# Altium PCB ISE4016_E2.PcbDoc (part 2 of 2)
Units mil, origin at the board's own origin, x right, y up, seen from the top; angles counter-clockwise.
Board outline 5600 x 2000 mil, 4 copper layers (Top Layer, InternalPlane1, MidLayer2, Bottom Layer), stack 59 mil thick; 110 components, 63 nets, 365 pads, 250 vias.
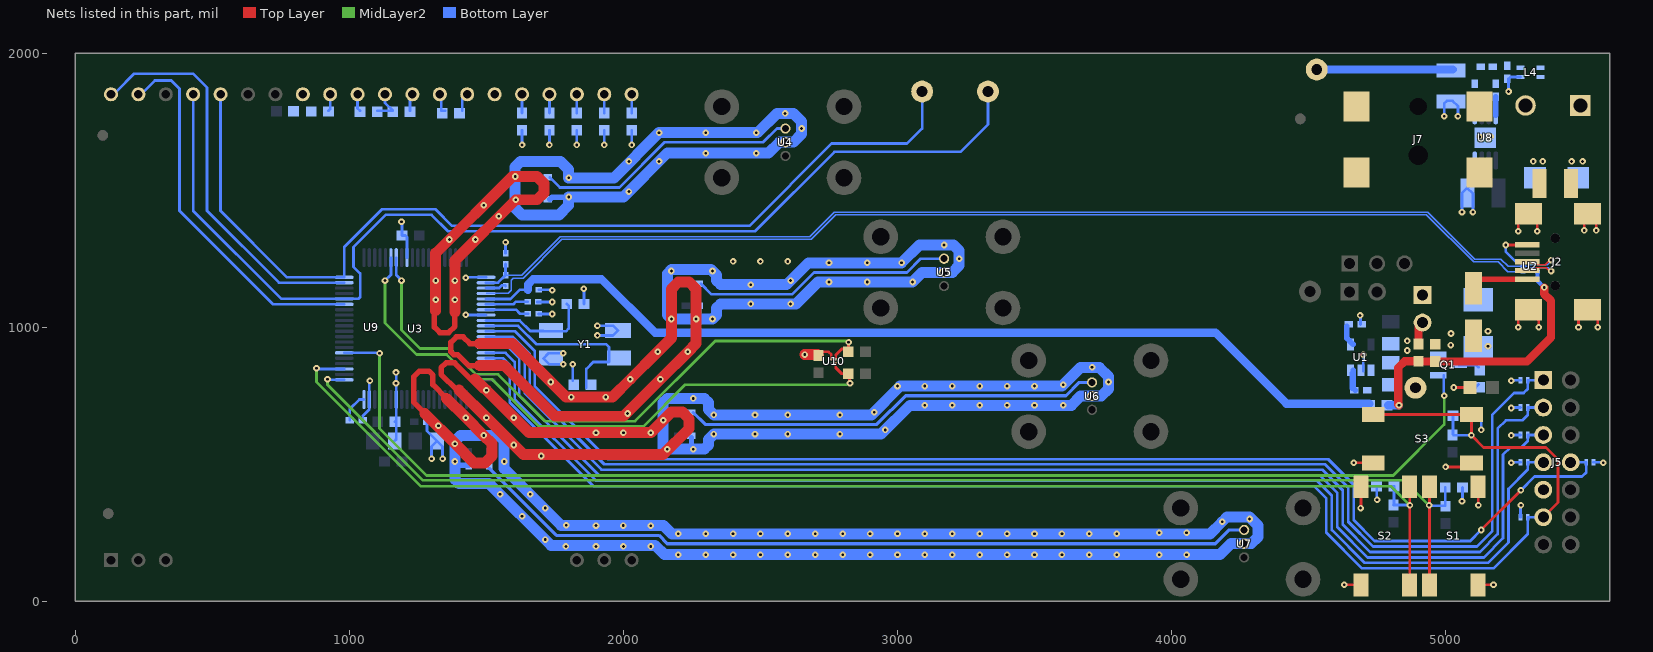
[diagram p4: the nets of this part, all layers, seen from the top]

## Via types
v1: diameter 24, hole 10, Top Layer to Bottom Layer, tented both sides, 246 vias
v2: diameter 22, hole 10, Top Layer to Bottom Layer, tented both sides, 4 vias

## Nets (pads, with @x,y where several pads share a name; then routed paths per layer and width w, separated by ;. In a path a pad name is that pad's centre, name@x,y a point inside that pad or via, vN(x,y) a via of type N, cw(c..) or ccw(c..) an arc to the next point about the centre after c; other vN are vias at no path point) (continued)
GND: C1.2 C2.2 C3.2 C4.2 C5.2 C6.2 C7.2 C8.2 C9.2 C10.2 C11.2 C12.2 C13.2 C14.2 C15.2 C16.2 C17.2 C18.2 C19.2 C21.2 C22.2 C23.2 C24.2 C28.2 C29.2 C30.2 C31.2 C32.2 C33.2 C34.2 C35.2 C36.2 C37.2 C38.2 D1.2 D2.2 D3.2 D4.2 D5.2 D7.2 D8.2 J2.5 J2.6 J2.7 J2.8 J2.9 J5.9 L4.3 Q1.2 R5.2 S1.3 S1.4 S2.3 S2.4 S3.3 S3.4 U1.2 U2.3 U3.14 U3.19 U3.49 U3.61 U3.68 U4.2 U5.2 U6.2 U7.2 U8.4 U8.9 U9.26 U9.33 U10.A2 Y1.2 Y1.4 | length 27028.8
  Top Layer w10: C38.2@2711.65,896.5 2725.16,910 2748.65,910 2758.65,900 U10.A2@2758.65,882.87 ; v1(4630,60) 4690.79,60 S2.4@4691.73,59.06 ; v1(4665,505) 4735.79,505 S3.3@4736.18,504.61 ; v1(4690,340) 4691.73,341.73 S2.3@4691.73,417.32 ; v1(5000,490) 5079.84,490 S3.4@5094.45,504.61 ; S1.3@5118.9,59.06 5119.84,60 v1(5175,60) ; S1.4@5118.9,417.32 5118.9,351.1 v1(5120,350) ; v1(5220,1300) J2.5@5291.77,1300 ; v1(5265,1000) 5265,1026.1 J2.9@5301.89,1062.99 5340,1024.88 v1(5340,1000) ; v1(5265,1350) J2.6@5265,1376.5 ; J2.6@5300,1386.5 J2.6@5336.89,1423.39 ; v1(5335,1350) J2.6@5335,1380.28 ; v1(5485,1000) 5485,1029.57 J2.8@5518.43,1062.99 5555,1026.42 v1(5555,1000) ; v1(5506,1353) J2.7@5506,1377.96 ; J2.7@5515,1384.96 J2.7@5553.43,1423.39 ; v1@5550,1350 J2.7@5550,1381.81
  Top Layer w20: 1285,675.5 1235,725.5 1235,820 1255,840 1290,840 1305,825 1305,790 1355,740 ; 1315,1055 1310,1050 1310,1000 1330,980 1362.43,980 1385,1002.57 1385,1050 ; 1400,770 1392.57,770 1335,827.57 1335,852.43 1352.57,870 1384,870 1486.5,767.5 ; 1475,860 1435,860 1395,900 1380,900 1370,910 1370,945 1390,965 1415,965 1440,940 1475,940
  Top Layer w40: 1275,685 v1(1385,575) 1455,505 1495,505 1520,530 1520,575 v1(1490,605) v1(1425,670) 1355,740 ; 1315,1060 1315,1270 1595,1550 1685,1550 1710,1525 1710,1490 1685,1465 v1(1607,1465) 1385,1243 1385,1056 ; 1400,770 v1(1500,670) v1(1600,570) 1635,535 2145,535 2240,630 2240,665 2215,690 2175,690 v1(2145,660) v1(2100,615) v1(2000,615) v1(1900,615) 1655,615 v1(1600,670) v1(1500,770) 1458.5,811.5 ; 1475,860 1565,860 1750,675 2000,675 v1(2135,810) v1(2235,910) 2265,940 v1(2265,1030) 2265,1140 2240,1165 2200,1165 2175,1140 2175,960 v1(2125,910) v1(2025,810) 1960,745 1790,745 1595,940 1475,940 ; v1(2661.65,900) 2708.15,900 C38.2@2711.65,896.5
  Bottom Layer w10: C11.2@1048.62,660 1048.62,676.49 1072.68,700.55 U3.19@1072.68,736.14 1072.68,802.68 v1(1075,805) ; C14.2@1165,585 1171.1,591.1 C16.2@1171.1,659.61 ; C16.2@1166.5,655 C16.2@1171.1,659.61 ; v1(1170,835) 1171.1,833.9 U3.14@1171.1,736.14 C16.2@1171.1,659.61 ; v1(1190,1385) 1191.53,1383.47 C15.2@1191.53,1334.4 1204.6,1334.4 1210.47,1328.53 U3.49@1210.47,1253.86 ; C17.2@1283.62,655 1283.62,621.38 C18.2@1320,585 ; v1(1300,520) 1300,565 C18.2@1320,585 ; v1(1340,520) 1340,565 C18.2@1320,585 ; v1(1425,1045) 1425.79,1044.21 U3.68@1498.86,1044.21 ; v1(1425,1180) 1427.01,1182.01 U3.61@1498.86,1182.01 ; R5.2@1570,1269.69 v1(1570,1310) ; v1(1630,1665) C29.2@1630,1718.5 ; C13.2@1685.69,1092 v1@1735,1092 ; C10.2@1690,1048 v1@1738.31,1048 ; C12.2@1690.69,1137 1738,1137 v1(1740,1135) ; v1(1730,1665) C30.2@1730,1718.5 ; v1(1780,865) 1728.98,865 1707.98,886 1726.98,905 v1(1780,905) ; C9.2@1815,805 v1(1815,865) ; v1(1830,1665) C31.2@1830,1718.5 ; v1(1855,1140) 1856.5,1138.5 C7.2@1856.5,1085 ; v1(1905,970) 1962.08,970 Y1.4@1980.08,988 1963.08,1005 v1(1905,1005) ; v1(1930,1665) C32.2@1930,1718.5 ; v1(2030,1665) C33.2@2030,1718.5 ; v1@4686.62,1041.62 v1(4688,1043) ; C4.2@4690,1010 v1@4690,1040 ; U1.2@4700,840 v1@4700,897.24 ; C8.2@4748.5,420 4748.5,371.5 v1(4750,370) ; v1(4995,1770) 4995,1816.26 5004.84,1826.1 5026.02,1826.1 5045,1807.13 v1(5045,1770) ; v1(5060,365) 5061.5,366.5 C6.2@5061.5,415 ; v1(5060,1420) 5060,1489.25 C23.2@5078.94,1508.19 ; C19.2@5089.82,677.27 5122.73,677.27 5130,670 v1(5130,625) ; v1(5100,1420) 5100,1487.13 C23.2@5078.94,1508.19 ; U8.4@5107.64,1610.51 5107.64,1536.89 C23.2@5078.94,1508.19 ; v1(5220,1300) 5220,1275 5253.31,1241.68 U2.3@5282.43,1241.68 ; v1(5230,1860) 5230,1906.38 5236.89,1913.27 L4.3@5273.58,1913.27 ; v1@5235,605 5236.81,606.81 D3.2@5273.3,606.81 ; v1(5240,505) 5241.81,506.81 D4.2@5273.3,506.81 ; v1(5240,705) 5241.81,706.81 D2.2@5273.3,706.81 ; v1(5240,805) 5241.81,806.81 D1.2@5273.3,806.81 ; D8.2@5273.3,306.81 5273.3,348.3 v1(5275,350) ; D5.2@5540.07,506.81 5573.19,506.81 v1(5575,505)
  Bottom Layer w20: v1(1385,510) 1398.62,496.38 C37.2@1436,496.38 ; C34.2@1731.5,1466.3 1740.2,1475 v1(1800,1475) ; C36.2@2248.35,597.2 2248.35,561.65 v1(2255,555) ; v1@2275.55,1030 C35.2@2275.55,1072.2
  Bottom Layer w40: v1(1791,277) 1773,277 1565,485 1565,585 1545,605 v1(1490,605) 1405,605 1385,585 v1(1385,575) v1(1385,510) 1385,445 1400,430 1510,430 1736.41,203.59 2115.94,203.59 2149.53,170 4177,170 4217,210 U7.2@4265,210 4291,210 4315,234 4315,276.04 4284.34,306.7 4201.7,306.7 v1(4185,290) 4141,246 2177,246 2146,277 v1@1793,277 ; v1(2265,1030) v1(2175,1030) 2160,1045 2160,1195 2175,1210 2320,1210 2340,1190 2340,1170 2355,1155 2595,1155 2675,1235 v1(3015,1235) 3080,1300 3205,1300 3225,1280 3225,1225 3200,1200 U5.2@3170.2,1200 ; v1@2275.55,1030 v1(2325,1030) 2340,1045 2340,1070 2355,1085 2630,1085 2710,1165 v1(3055,1165) 3090,1200 U5.2@3170,1200 ; U4.2@2591,1675 2620,1675 2650,1705 2650,1750 2620,1780 2560,1780 2490,1710 v1(2130,1710) 1965,1545 v1(1800,1545) 1800,1575 1770,1605 1625,1605 1605,1585 1605,1435 1630,1410 1765,1410 1800,1445 v1(1800,1475) 2000,1475 2160,1635 2529,1635 2569,1675 U4.2@2598.38,1675 ; 2145,560 2150,555 v1(2160,555) v1(2255,555) 2295,555 2310,570 2310,590 v1(2330,610) v1(2600,610) 2940,610 3045,715 3635,715 3668.54,748.54 U6.2@3710,748.54 3743.55,748.55 3770,775 3770,820 3736.46,853.54 v1(3710,853.54) 3668.54,853.54 3600,785 v1(3500,785) v1(3400,785) v1(3300,785) v1(3200,785) v1(3100,785) 3010,785 2905,680 v1(2330,680) 2310,700 2310,725 2295,740 2160,740 2145,725 v1(2145,660) 2145,560
  other v1: 2200,170 2300,170 2400,170 2500,170 2600,170 2700,170 2800,170 2900,170 3000,170 3100,170 3200,170 3300,170 3400,170 3500,170 3600,170 3700,170 3800,170 3955,170 4055,170 1790,200 1900,200 2000,200 2100,200 1715,225 2200,246 2300,246 2400,246 2500,246 2600,246 2700,246 2800,246 2900,246 3000,246 3100,246 3200,246 3300,246 3400,246 3500,246 3600,246 3700,246 3800,246 3955,250 4055,250 2100,275 1900,276 1999,276 4285,300 1630,310 1715,340 1550,390 1660,390 1565,510 1700,530 5240,605 2480,610 2790,610 2955,625 1325,640 2480,680 2600,680 2790,680 2015,685 2915,690 3100,715 3200,715 3300,715 3400,715 3500,715 3605,715 2255,740 1810,745 1935,745 3000,785 3605,790 1170,795 1735,800 3770,800 4700,900 4860,915 5155,930 5019,934.73 4860,950 5020,977 5155,985 1740,1048 2465,1085 2610,1085 1740,1092 1315,1100 1385,1100 2465,1155 2750,1165 2890,1165 1315,1170 1385,1170 2610,1170 2175,1205 2325,1205 2750,1235 2890,1235 2400,1240 2500,1240 2600,1240 3225,1250 3170,1300 1365,1320 1460,1320 5550,1353 1545,1405 1490,1445 2020,1495 1605,1550 2020,1605 2130,1605 2300,1635 2485,1635 5125,1695 5165,1695 2300,1710 2485,1710 2650,1725 2590,1780
NCS_DISP: U3.39 U9.40 | length 1457.6
  Bottom Layer w10: U9.40@130,1860 150,1860 215,1925 430,1925 480,1875 480,1425 742.68,1162.32 U3.39@981.14,1162.32
NetC4_1: C4.1 U1.4 | length 75.7
  Bottom Layer w20: C4.1@4640,1003.62 4640,959.84 4650,949.84 U1.4@4662.6,937.24
NetC5_1: C5.1 D7.1 J1.1 J2.1 | length 119
  Top Layer w20: 5134,1175 J2.1@5252.95,1175
NetC13_1: C13.1 U3.66 | length 155.4
  Bottom Layer w10: U3.66@1498.86,1083.58 1598.58,1083.58 1608,1093 C13.1@1650.32,1093
NetC20_1: C20.1 D10.2 J6.1 J7.1 J7.1A L4.1
  other v1: 5460,1605 5500,1605
NetC20_2: C20.2 D10.1 J6.2 J7.2 J7.3 L4.4
  other v1: 5320,1605 5355,1605
NetC21_1: C21.1 D9.2 L4.2
NetC25_1: C25.1 U9.31 | length 73.5
  Bottom Layer w10: U9.31@1030,1860 1030,1798.5 C25.1@1038.5,1790
NetC25_2: C25.2 C26.1 U9.30 | length 138.8
  Bottom Layer w10: C25.2@1101.5,1790 1158.5,1790 1130,1818.5 U9.30@1130,1860
NetC26_2: C26.2 U9.29 | length 73.5
  Bottom Layer w10: C26.2@1221.5,1790 1221.5,1851.5 U9.29@1230,1860
NetC27_1: C27.1 U9.28 | length 85.6
  Bottom Layer w10: U9.28@1330,1860 1335,1855 1335,1790 C27.1@1348.5,1790
NetC27_2: C27.2 U9.27 | length 77.7
  Bottom Layer w10: C27.2@1411.5,1790 1411.5,1841.5 U9.27@1430,1860
NetC28_1: C28.1 U9.32 | length 72.7
  Bottom Layer w10: C28.1@923.45,1790 930,1796.56 U9.32@930,1860
NetC29_1: C29.1 U9.25 | length 78.5
  Bottom Layer w10: C29.1@1630,1781.5 U9.25@1630,1860
NetC30_1: C30.1 U9.24 | length 78.5
  Bottom Layer w10: C30.1@1730,1781.5 U9.24@1730,1860
NetC31_1: C31.1 U9.23 | length 78.5
  Bottom Layer w10: C31.1@1830,1781.5 U9.23@1830,1860
NetC32_1: C32.1 U9.22 | length 78.5
  Bottom Layer w10: C32.1@1930,1781.5 U9.22@1930,1860
NetC33_1: C33.1 U9.21 | length 78.5
  Bottom Layer w10: C33.1@2030,1781.5 U9.21@2030,1860
NetD6_2: D6.2 R3.2 | length 163.7
  Top Layer w10: v1(5030,780) D6.2@5098.66,780
  Bottom Layer w10: v1(5030,780) 5109.76,780 R3.2@5120.53,790.77
NetJ1_2: J1.2 L1.1 | length 84.7
  Top Layer w30: L1.1@4901,938.5 4901,1002 J1.2@4916,1017
NetQ1_1: Q1.1 U3.26 | length 4606.8
  MidLayer2 w10: v1(1110,905) 1110,630 1281,459 4809,459 4995,645 v1@4995,747
  Bottom Layer w10: U3.26@981.14,906.42 1099.58,906.42 v1@1100,906 ; v1@4993.13,747 Q1.1@4993.13,824.87
  other v1: 4995,750
NetQ1_3: Q1.3 R3.1 | length 76.1
  Bottom Layer w10: Q1.3@5047.93,862.27 5112.03,862.27 R3.1@5120.53,853.77
NetR1_1: R1.1 U1.3 | length 129.8
  Bottom Layer w20: R1.1@4659.38,778 4660,778 U1.3@4660,831.35 ; U1.3@4662.6,842.76 4662.6,777.4 R1.1@4670,770
NetR8_2: R8.2 U8.8 | length 67.7
  Bottom Layer w20: U8.8@5183.39,1773.68 R8.2@5183.39,1841.38
NetR9_2: R9.2 U8.5 | length 68.3
  Bottom Layer w20: U8.5@5106.61,1773.68 5107.2,1774.26 R9.2@5107.2,1841.78
NetR10_1: R10.1 U4.3 | length 963.6
  Bottom Layer w10: R10.1@1731.5,1546.3 1767.8,1510 1985,1510 2150,1675 2510,1675 2560,1725 U4.3@2591,1725
NetR11_1: R11.1 U5.3 | length 957.8
  Bottom Layer w10: R11.1@2282.05,1158.7 2320.75,1120 2615,1120 2695,1200 3035,1200 3085,1250 U5.3@3170,1250
NetR12_1: R12.1 U6.3 | length 1543.9
  Bottom Layer w12: R12.1@2254.84,688.7 2298.54,645 2925,645 3030,750 3615,750 3663.54,798.54 U6.3@3710,798.54 ; U6.3@3715,793.54 U6.3@3720,798.54
NetR13_1: R13.1 U7.3 | length 2889.9
  Bottom Layer w12: R13.1@1510,485.57 1755.57,240 2130,240 2160,210 4160,210 4210,260 U7.3@4265,260
NRST_DISP: U3.35 U9.39 | length 1366.6
  Bottom Layer w10: U9.39@230,1860 250,1860 290,1900 350,1900 380,1870 380,1425 721.42,1083.58 U3.35@981.14,1083.58
NRST_MSP: C19.1 D8.1 J5.11 R7.1 S3.1 S3.2 U3.76 | length 5599.6
  Top Layer w10: S3.1@4736.18,681.77 S3.2@5094.45,681.77 v1(5094.45,605.55) 5138.67,561.33 5366.48,561.33 5410,517.81 5410,360.13 J5.11@5356.69,306.81
  Bottom Layer w10: U3.76@1498.86,886.73 1560.27,886.73 1585,862 1585,725 1890,420 4520,420 4565,375 4565,250 4695,120 5175,120 5300.07,245.07 D8.1@5300.07,306.81 J5.11@5356.69,306.81 ; C19.1@5026.83,677.27 5026.83,608.33 5029.61,605.55 v1(5094.45,605.55)
PUR_1: R6.1 U3.63 | length 76.5
  Bottom Layer w10: U3.63@1498.86,1142.64 1546.54,1142.64 1556.8,1152.9 1567.41,1152.9 R6.1@1570,1150.32
SCL_DISP: TP5.1 U3.36 U9.37 | length 4031.8
  Bottom Layer w10: U9.37@430,1860 430,1425 750.95,1104.05 1034.05,1104.05 1039.2,1109.2 1039.2,1195.8 1015,1220 1015,1292.5 1132.5,1410 1300,1410 1360,1350 2480,1350 2770,1640 3230,1640 3330,1740 3330,1835 TP5.1@3320,1845
SCL_TEMP: R14.1 U3.47 U10.B2 | length 2265.9
  Top Layer w10: U10.B2@2774.65,882.87 2774.65,898 2796.65,920 R14.1@2815.16,920 ; v1(2821.65,945) 2821.65,913.5 R14.1@2825.16,910
  MidLayer2 w10: v1(1190,1170) 1190,990 1257.5,922.5 1367.5,922.5 1462,828 1542,828 1713,657 2042,657 2335,950 2816.65,950 v1(2821.65,945)
  Bottom Layer w10: U3.47@1171.1,1253.86 1171.1,1190 1190,1171.1 v1(1190,1170)
SDA_TEMP: R15.1 U3.46 U10.B1 | length 2265.9
  Top Layer w10: U10.B1@2774.65,867.13 2774.65,852 2796.65,830 R15.1@2815.16,830 ; R15.1@2825.16,830 2825.16,796.5 v1(2826.65,795)
  MidLayer2 w10: v1(1130,1170) 1130,1015 1245,900 1355,900 1445,810 1520,810 1692,638 2073,638 2225,790 2821.65,790 v1(2826.65,795)
  Bottom Layer w10: v1(1130,1170) 1151.42,1191.42 U3.46@1151.42,1253.86
SI_DISP: TP4.1 U3.40 U9.36 | length 3570.4
  Bottom Layer w10: U9.36@530,1860 530,1425 772.99,1182.01 U3.40@981.14,1182.01 981.14,1293.14 1118,1430 1315,1430 1375,1370 2460,1370 2760,1670 3035,1670 3090,1725 TP4.1@3090,1860
TCK: D4.1 J5.7 U3.75 | length 4610
  Bottom Layer w10: U3.75@1498.86,906.42 1569.58,906.42 1603,873 1603,737 1900,440 4530,440 4585,385 4585,260 4705,140 5155,140 5230,215 5230,410 5300.07,480.07 D4.1@5300.07,506.81 J5.7@5356.69,506.81
TDI: D2.1 J5.3 U3.73 | length 4786.5
  Bottom Layer w10: U3.73@1498.86,945.79 1586.21,945.79 1640,892 1640,760 1920,480 4550,480 4625,405 4625,280 4725,180 5125,180 5190,245 5190,630 5220,660 5280,660 5300.07,680.07 D2.1@5300.07,706.81 J5.3@5356.69,706.81 J5.3@5356.69,705.32
TDO: D1.1 J5.1 U3.72 | length 4843.2
  Bottom Layer w10: U3.72@1498.86,965.47 1594.53,965.47 1658,902 1658,772 1930,500 4560,500 4645,415 4645,290 4735,200 5115,200 5170,255 5170,680 5250,760 5285,760 5300.07,775.07 D1.1@5300.07,806.81 J5.1@5356.69,806.81
TEST_MSP: D5.1 J5.8 U3.71 | length 4679.4
  Top Layer w10: v1(5130,260) v1(5275,405)
  Bottom Layer w10: U3.71@1498.86,985.16 1604.84,985.16 1676,914 1676,785 1943,518 4572,518 4665,425 4665,296.21 4741.21,220 5090,220 v1(5130,260) ; v1(5275,405) 5325,455 5498.3,455 5513.3,470 D5.1@5513.3,506.81 J5.8@5456.69,506.81
TMS: D3.1 J5.5 U3.74 | length 4704.5
  Bottom Layer w10: U3.74@1498.86,926.1 1579.9,926.1 1620,886 1620,750 1910,460 4540,460 4605,395 4605,270 4715,160 5140,160 5210,230 5210,535 5236.33,561.33 5276.33,561.33 5300.07,585.07 D3.1@5300.07,606.81 J5.5@5356.69,606.81
USB_D_N: J2.2 U2.1 U3.64 | length 4194.1
  Top Layer w5.3: J2.2@5327,1206.69 5327,1212 5332.7,1217.7 5367.27,1217.7 5379.97,1205 v1(5385,1205)
  Bottom Layer w5.3: U3.64@1498.86,1122.95 1579.35,1122.95 1590.49,1134.09 1590.49,1171.79 1598.09,1179.39 1633.95,1179.39 1774.57,1320 2684.57,1320 2774.27,1409.7 4930.3,1409.7 5102,1238 5192,1238 5227.69,1202.31 U2.1@5282.43,1202.31 5283.11,1203 5297,1203 5310,1216 5374,1216 v1(5385,1205)
USB_D_P: J2.3 R5.1 R6.2 U2.2 U3.62 | length 4203.2
  Top Layer w5.3: J2.3@5325,1238.19 5325,1235 5332,1228 5363,1228 5380,1245 v1(5385,1245)
  Bottom Layer w5.3: R6.2@1570,1189.69 1629.69,1189.69 1770.3,1330.3 2680.3,1330.3 2770,1420 4934.57,1420 5106.27,1248.3 5201.7,1248.3 5228,1222 U2.2@5282.43,1222 5301.43,1222 5306.43,1227 5372,1227 5387.5,1242.5 v1(5385,1245)
  Bottom Layer w10: U3.62@1498.86,1162.32 1541.97,1162.32 1569.33,1189.69 R6.2@1570,1189.69 R5.1@1570,1230.32
USER_BUTTON1: C6.1 R2.1 S1.1 S1.2 U3.21 | length 4768.8
  Top Layer w10: S1.1@4941.73,59.06 S1.2@4941.73,417.32
  MidLayer2 w10: v1(920,810) 920,790 1269,441 4849,441 v1(4940,350)
  Bottom Layer w10: v1(920,810) 922.01,807.99 U3.21@981.14,807.99 ; v1(4940,350) 4942.01,347.99 4998.5,347.99 C6.1@4998.5,415
USER_BUTTON2: C8.1 R4.1 S2.1 S2.2 U3.23 | length 4816.6
  Top Layer w10: S2.2@4868.9,59.06 S2.1@4868.9,417.32
  MidLayer2 w10: v1(880,850) 880,800 1260,420 4800,420 v1(4870,350)
  Bottom Layer w10: v1(880,850) 882.64,847.36 U3.23@981.14,847.36 ; C8.1@4811.5,420 4811.5,352.99 R4.1@4810,351.5 4868.5,351.5 v1(4870,350)
V18_1: C10.1 U3.67 | length 158.6
  Bottom Layer w10: U3.67@1498.86,1063.9 1608.1,1063.9 1623,1049 C10.1@1651.32,1049
VBUS: C2.1 L1.2 L2.1 U2.5 | length 1039.6
  Top Layer w30: v1(4830,715) 4827,718 4827,852 4850.5,875.5 L1.2@4901,875.5 ; L1.2@4901,874.33 5297.11,874.33 5385,962.22 5385,1096.75 5360,1121.75 v1(5360,1145)
  Bottom Layer w15: U2.5@5335.57,1200 5335.57,1169.43 v1(5360,1145)
  Bottom Layer w30: L2.1@4791,715 v1(4830,715)
VBUS_FLT: C3.1 C12.1 L2.2 R1.2 TP1.1 U1.1 U3.65 | length 3452
  Bottom Layer w10: U3.65@1498.86,1103.27 1588.27,1103.27 1622,1137 C12.1@1651.32,1137
  Bottom Layer w30: C12.1@1651.32,1137 1651.32,1156.32 1670,1175 1920,1175 2115,980 4160,980 4419,721 L2.2@4721.82,721
VCORE1: C11.1 U3.20 | length 107.4
  Bottom Layer w10: C11.1@1001.38,660 1001.38,701.38 1036.14,736.14 U3.20@1052.99,736.14
VIN_24V: C22.1 D9.1 R8.1 R9.1 TP3.1 | length 496.1
  Bottom Layer w30: TP3.1@4529.88,1940.28 C22.1@5026.02,1940.28
XT2IN1: C7.1 U3.69 Y1.1 | length 455.3
  Bottom Layer w10: U3.69@1498.86,1024.53 1621.47,1024.53 1660,986 1707.98,986 Y1.1@1708.98,985 ; 1668,985 Y1.1@1708.98,985 ; C7.1@1793.5,1085 1800,1078.5 1800,995 1790,985 Y1.1@1708.98,985
XT2OUT1: C9.1 U3.70 Y1.3 | length 695
  Bottom Layer w10: U3.70@1498.86,1004.84 1615.16,1004.84 1682,938 1936,938 1947.02,926.98 1947.02,873 1890,873 1864.5,847.5 C9.1@1864.5,780
pads on no net: FID1.1 FID2.1 FID3.1 FID4.1 FID5.1 FID6.1 J2.4 J2.10 J2.11 J5.2 J5.6 J5.10 J5.12 J5.13 J5.14 J7.MH1 J7.MH2 SH-J1.0 SH-J2.0 U2.4 U3.1 U3.2 U3.3 U3.4 U3.5 U3.6 U3.7 U3.8 U3.9 U3.10 U3.12 U3.13 U3.15 U3.16 U3.17 U3.22 U3.24 U3.25 U3.27 U3.28 U3.29 U3.30 U3.31 U3.32 U3.33 U3.37 U3.38 U3.41 U3.42 U3.43 U3.44 U3.45 U3.48 U3.51 U3.52 U3.53 U3.54 U3.55 U3.56 U3.57 U3.58 U3.59 U3.60 U8.2 U8.3 U8.6 U8.7 U9.1 U9.2 U9.3 U9.18 U9.19 U9.20 Z1.1 Z1.2 Z1.3 Z1.4 Z2.1 Z2.2 Z2.3 Z2.4 Z3.1 Z3.2 Z3.3 Z3.4 Z4.1 Z4.2 Z4.3 Z4.4

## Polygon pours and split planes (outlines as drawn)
GND on MidLayer2 "GND" (solid, remove dead copper, pour order 3): 10,1990 10,10 5590,10 5590,1990
NetC20_1 on Top Layer "GND" (solid, remove dead copper, pour order 4): 5200,1530 5200,1890 5445,1890 5445,1485 5575,1485 5575,1970 5050,1970 5050,1530
GND on InternalPlane1 (split plane): 5579.9,20.1 20.1,20.1 20.1,1979.9 5579.9,1979.9

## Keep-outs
Keep-Out Layer:
  text ".Layer_Name" at 577,-858.49 h60

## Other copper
Top Layer:
  region net NetC5_1: 4875,1160 5030,1160 5030,1220 5175,1220 5175,1045 4960,1045 4960,1065 4875,1065
  region net GND: 4935,960 4935,905 5190,905 5190,1030 5000,1030 5000,960
  region net NetC20_2: 4615,1900 4615,1440 5230,1440 5230,1460 5235,1465 5390,1465 5395,1470 5395,1839 5217,1839 5217,1500 4750,1500 4750,1900
  text ".Layer_Name" at 577,-858.49 h60
MidLayer2:
  text ".Layer_Name" at 577,-858.49 h60
Bottom Layer:
  region net +3P3_USB: 4560,1305 4560,1210 4410,1210 4410,1065 4700,1065 4700,1305
  region net +3P3V: 1080,675 1125,675 1125,545 1155,545 1155,470 990,470 990,635 1080,635
  region net AVCC: 1205,680 1205,545 1165,545 1165,470 1270,470 1270,630 1255,630 1255,680
  region net GND: 780,1885 780,1755 885,1755 885,1885
  region net NetC25_2: 1080,1890 1080,1755 1185,1755 1185,1890
  region net GND: 5180,1025 5000,1025 5000,965 4760,965 4760,840 4835,840 4835,885 5180,885
  region net VIN_24V: 4950,1970 4950,1870 5190,1870 5190,1920 5144,1920 5144,1970
  region net NetC21_1: 5155,1935 5300,1935 5300,1980 5155,1980
  region net VBUS_FLT: 4720,870 4720,810 4690,810 4690,690 4745,690 4745,760 4850,760 4850,735 4935,735 4935,820 4750,820 4750,870
  region net NetC5_1: 4880,1145 4880,1075 5045,1075 5045,1045 5175,1045 5175,1145
  region net NetC20_1: 5330,1935 5330,1980 5550,1980 5550,1480 5400,1480 5400,1935
  region net NetC20_2: 5385,1925 5300,1925 5300,1860 5250,1860 5250,1485 5370,1485 5370,1900 5385,1900
  text ".Layer_Name" at 577,-858.49 h60
InternalPlane1 (plane layer: these items are gaps in the copper):
  text ".Layer_Name" at 577,-858.49 h60

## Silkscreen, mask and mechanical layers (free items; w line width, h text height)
Top Overlay:
  text "SI_DISP" at 3030,1940 h50
  text "SCL_DISP" at 3230,1940 h50
  text "VIN_24V" at 4400,1840 h50
  text "+3P3_USB" at 4360,1210 h50
  text "VBUS" at 4710,850 h50
  text "FLT" at 4730,805 h50
  text ".Layer_Name" at 582,-858.49 h60
Bottom Overlay:
  rectangle: 569,250 869,350
  text ".PRJ_Number" at 1535,260 h60
  text ".PCB_Rev" at 1530,140 h60
  text ".Layer_Name" at 577,-858.49 h60
Top Paste:
  text ".Layer_Name" at 577,-858.49 h60
Bottom Paste:
  text ".Layer_Name" at 577,-858.49 h60
Top Solder:
  text ".Layer_Name" at 577,-858.49 h60
  text ".Layer_Name" at 577,-858.49 h60
Bottom Solder:
  text ".Layer_Name" at 577,-858.49 h60
Drill Guide:
  text ".Layer_Name" at 577,-858.49 h60
M1 Board Outline:
  lines w8: 5000,0 0,0 0,2000 5000,2000 ; 5600,0 5600,2000
  text ".Layer_Name" at 577,-858.49 h60
M2 Board Dimensions:
  rectangle: -0.5,-285.5 124.5,-160.5
  rectangle: 124.5,-410.5 499.5,-285.5
  lines w7: -0.5,-285.5 999.5,-285.5 ; 124.5,-410.5 124.5,-160.5 ; 249.5,-410.5 249.5,-160.5 ; 499.5,-410.5 499.5,-160.5 ; 749.5,-410.5 749.5,-160.5 ; -0.5,-410.5 999.5,-410.5 999.5,-160.5 -0.5,-160.5 -0.5,-410.5
  lines w10: -0.5,-475.5 -0.5,-455.5 ; 59.5,-485.5 -0.5,-465.5 ; 59.5,-445.5 -0.5,-465.5 ; 223.58,-465.5 -0.5,-465.5 ; 775.42,-465.5 999.5,-465.5 ; 939.5,-485.5 999.5,-465.5 ; 939.5,-445.5 999.5,-465.5 ; 999.5,-475.5 999.5,-455.5
  text "1000 (mil)" at 233.58,-501.49 h60
  text ".Layer_Name" at 577,-858.49 h60
M3 3D STEP Top:
  text ".Layer_Name" at 577,-858.49 h60
M4 3D STEP Bottom:
  text ".Layer_Name" at 577,-858.49 h60
M5 Assembly Top:
  lines w10: -292,-930.17 6308,-930.17 ; -292,-726.83 6310,-726.83 ; -292,-523.5 -292,-1133.5 3713,-1133.5 6310,-1133.5 6310,-523.5 -291.5,-523.5 -291.5,-1133.5 1284,-1133.5 ; 2173,-1133.5 2173,-523.5 ; 3440,-726.83 3440,-523.5 ; 4280,-726.83 4280,-523.5 ; 4902,-1140 4902,-937.17
  text "COMPONENTS MARKED 'DNP' SHOULD NOT BE POPULATED." at 1153.5,-318.5 h60
  text "ASSEMBLY VARIANT:" at 1153,-434 h60
  text ".VariantName" at 2189,-434 h60
  text "PCB VIEWED FROM TOP SIDE" at -228.5,-655.67 h60
  text "BOARD #:" at 2248,-655.67 h60
  text ".PRJ_Number" at 2793.5,-655.67 h60
  text "REV:" at 3638,-655.67 h60
  text ".PCB_Rev" at 3929.5,-655.67 h60
  text "SVN REV:" at 4476,-655.67 h60
  text ".VersionControl_RevNumber" at 4982,-655.67 h60
  text "IGNORE ->" at -228.5,-858.49 h60
  text "PLOT NAME =" at -228.5,-1064.34 h60
  text ".plot_File_Name" at 577,-1064.34 h60
  text "GENERATED    :" at 2250,-1064.34 h60
  text ".Print_Date" at 3119.5,-1064.34 h60
  text ".Print_Time" at 3848.5,-1064.34 h60
  text "TEXAS INSTRUMENTS" at 5113,-1064.34 h60
M6 Assembly Bottom:
  lines w10: -292.5,-727.33 6309.5,-727.33 ; -290.5,-930.67 6309.5,-930.67 ; 1115.5,-1140.5 1115.5,-937.67 ; 1737.5,-727.33 1737.5,-524 ; 2577.5,-727.33 2577.5,-524 ; 3844.5,-1134 3844.5,-524 ; 4733.5,-1134 6309,-1134 6309,-524 -292.5,-524 -292.5,-1134 2304.5,-1134 6309.5,-1134 6309.5,-524
  text "COMPONENTS MARKED 'DNP' SHOULD NOT BE POPULATED." at 6102,-318 h60
  text ".VariantName" at 5058,-434 h60
  text "ASSEMBLY VARIANT:" at 6097,-434 h60
  text ".VersionControl_RevNumber" at 1035.5,-656.17 h60
  text "SVN REV:" at 1541.5,-656.17 h60
  text ".PCB_Rev" at 2088,-656.17 h60
  text "REV:" at 2379.5,-656.17 h60
  text ".PRJ_Number" at 3224,-656.17 h60
  text "BOARD #:" at 3769.5,-656.17 h60
  text "PCB VIEWED FROM BOTTOM SIDE" at 6246,-656.17 h60
  text "IGNORE ->" at 2547.85,-858.49 h60
  text "TEXAS INSTRUMENTS" at 904.5,-1064.84 h60
  text ".Print_Time" at 2169,-1064.84 h60
  text ".Print_Date" at 2898,-1064.84 h60
  text "GENERATED    :" at 3767.5,-1064.84 h60
  text ".plot_File_Name" at 5440.5,-1064.84 h60
  text "PLOT NAME =" at 6246,-1064.84 h60
M9 Title Sheet:
  drawing of 57 lines, arcs and shapes, not listed
  text "1" at 739.84,8036.5 h70
  text "2" at 3235.5,8036.5 h70
  text "3" at 5724.84,8036.5 h70
  text "4" at 8231.51,8036.5 h70
  text "5" at 10730.5,8036.5 h70
  text "6" at 13235.5,8036.5 h70
  text "A" at -416.5,6893.5 h70
  text "A" at 14383.5,6893.5 h70
  text "B" at -416.5,4513.5 h70
  text "B" at 14383.5,4513.5 h70
  text "C" at -416.5,2138.5 h70
  text "C" at 14383.5,2138.5 h70
  text "PROJECT TITLE:" at 11343.5,277.5 h45
  text ".PRJ_Title" at 11393.5,144.17 h70
  text "DESIGNED FOR:" at 11343.5,-23.5 h45
  text ".PRJ_Customer" at 11393.5,-163.5 h70
  text "D" at -416.5,-231.5 h70
  text "D" at 14383.5,-231.5 h70
  text "FILE NAME:" at 11343.5,-323.5 h45
  text ".PCB_File_Name_No_Path" at 11393.5,-443.5 h70
  text "Texas Instruments (TI) and/or its licensors do not warrant the accuracy or completeness of this specification" at 6374,-605.34 h45
  text "ENGINEER:" at 11343.5,-613.5 h45
  text "LAYOUT BY:" at 12848.5,-613.5 h45
  text "or any information contained therein. TI and/or its licensors do not warrant that this design will meet" at 6329.01,-718 h45
  text ".PRJ_Engineer" at 11393.5,-768.49 h70
  text ".PCB_Layout" at 12899,-768.49 h70
  text "the specifications, will be suitable for your application or fit for any particular purpose, or will operate in" at 6329.01,-830.67 h45
  text ".Layer_Name" at 577,-858.49 h60
  text "ALTIUM DESIGNER VERSION:" at 12848.5,-923.5 h45
  text "an implementation. TI and/or its licensors do not warrant that the design is production worthy. You should" at 6329.01,-943.33 h45
  text "completely validate and test your design implementation to confirm the system functionality for your application." at 6374,-1056 h45
  text ".print_Scale" at 11393.5,-1056.83 h70
  text ".Application_BuildNumber" at 12899,-1056.83 h70
  text "1" at 739.84,-1263.5 h70
  text "2" at 3235.5,-1263.5 h70
  text "3" at 5724.84,-1263.5 h70
  text "4" at 8231.51,-1263.5 h70
  text "5" at 10730.5,-1263.5 h70
  text "6" at 13235.5,-1263.5 h70
M10 Fab Notes:
  drawing of 212 lines, arcs and shapes, not listed
  text "DESIGN INFORMATION" at 12381.02,6810 h60
  text "(REFER ALSO ARRAY/PANEL PROFILING INFORMATION)" at 12019.46,6648.29 h60
  text "BOARD SIZE" at 11333.46,6644 h60
  text "2000MIL" at 11795.78,6516.18 h60
  text "X" at 12301.46,6516.18 h60
  text "5600MIL" at 12532.78,6516.18 h60
  text "Number of Layers :" at 11736.46,6319 h60
  text "4" at 12831.27,6309 h60
  text "MIN. TRACK WIDTH:" at 11736.46,6180 h60
  text "8" at 12832.7,6180 h60
  text "MIL" at 12987.46,6180 h60
  text "MIN. CLEARANCE:" at 11736.46,6048 h60
  text "8" at 12832.7,6048 h60
  text "MIL" at 12987.46,6048 h60
  text "MIN. VIA PAD SIZE:" at 11736.46,5916 h60
  text "22" at 12802.71,5916 h60
  text "MIL" at 12987.46,5916 h60
  text "0.05mm (2MIL)" at 12431.46,5774.29 h60
  text "MINIMUM ANNULAR RING" at 11407.23,5770 h60
  text "EXTERNAL" at 13139.46,5770 h60
  text "PER" at 11607.23,5652 h60
  text "IPC-D-275 CLASS 2 LEVEL C" at 11827.23,5652 h60
  text "MIL, HOLES" at 13315.46,5539.71 h60
  text "+/-" at 12923,5539 h60
  text "+/-" at 13777,5539 h60
  text "REGISTRATION TOLERANCES:" at 11407.23,5534 h60
  text "METAL" at 12607,5534 h60
  text "5" at 13183.2,5534 h60
  text "3" at 14016.2,5534 h60
  text "MIL" at 14132.46,5534 h60
  text "MATERIAL:" at 11332.46,5324.54 h60
  text "FR-4 High Tg" at 12318.9,5184.21 h60
  text "FR-408" at 11753.46,5175.64 h60
  text "X" at 12165.46,5175.64 h60
  text "OTHER" at 13241.46,5175.64 h60
  text "62 MIL (1.6mm) +/-10%" at 12073.56,5012.92 h60
  text "THICKNESS:" at 11407.23,5008.64 h60
  text "X" at 11945.4,5008.64 h60
  text "OTHER" at 13358.46,5008.64 h60
  text "TOLERANCE:" at 11407.23,4850.64 h60
  text "X" at 12246.53,4850.64 h60
  text "ANSI IPC-6012 TYPE 3 CLASS 2" at 12433.48,4850.64 h60
  text "OTHER +/-" at 12433.46,4694.64 h60
  text "BOW & TWIST:" at 11407.23,4537.64 h60
  text "X" at 12246.53,4537.64 h60
  text "ANSI IPC-6012 TYPE 3 CLASS 2" at 12433.48,4537.64 h60
  text "OTHER +/-" at 12433.46,4379.13 h60
  text "COPPER THICKNESS (FINISHED):" at 11332.46,4243.64 h60
  text "1.4MIL (1oz)" at 12212.46,4090.92 h60
  text "2MIL (1.4oz)" at 12979.46,4090.92 h60
  text "2.8MIL (2oz)" at 13706.46,4090.92 h60
  text "OUTER:" at 11689.46,4086.64 h60
  text "X" at 12084,4086 h60
  text "1.4MIL (1oz)" at 12212.46,3933.92 h60
  text "2.8MIL (2oz)" at 12979.46,3933.92 h60
  text "N/A" at 13706,3934.29 h60
  text "INNER SIGNAL:" at 11400.38,3929.64 h60
  text "X" at 12085.42,3929.64 h60
  text "DRILLING:" at 11332.46,3790.64 h60
  text "REFERENCE:" at 11407.23,3673.64 h60
  text "X" at 12055.46,3673.64 h60
  text "AS SHOWN" at 12242.46,3673.64 h60
  text "X" at 12956.46,3673.64 h60
  text "NC_DRILL FILES" at 13093.46,3673.64 h60
  text "PTH MIN COPPER THICKNESS:" at 11407.23,3515.64 h60
  text "X" at 12757.46,3515.64 h60
  text "1MIL" at 12894.46,3515.64 h60
  text "OTHER" at 13391.46,3515.64 h60
  text "BOARD FINISH:" at 11332.46,3356.64 h60
  text "SILKSCREEN:" at 11487.68,3238.64 h60
  text "X" at 12436.46,3238.64 h60
  text "TOP" at 12562.46,3238.64 h60
  text "X" at 12946.46,3238.64 h60
  text "BOTTOM" at 13073.46,3238.64 h60
  text "SILKSCREEN COLOR:" at 11487.68,3071.64 h60
  text "X" at 12435.42,3071.64 h60
  text "WHITE" at 12562.46,3071.64 h60
  text "OTHER" at 13073.46,3071.64 h60
  text "SOLDER RESIST COLOR:" at 11487.68,2901.64 h60
  text "X" at 13150,2745 h60
  text "GREEN" at 12182.46,2742.44 h60
  text "BLUE" at 12773.46,2742.44 h60
  text "OTHER" at 13311.46,2742.44 h60
  text "BLACK" at 13685,2730 h60
  text "IMMERSION GOLD (ENIG)" at 12393.46,2553.92 h60
  text "ENEPIG" at 13731,2550.64 h60
  text "SURFACE FINISH:" at 11332.46,2549.64 h60
  text "X" at 12206.51,2549.64 h60
  text "IMM. TIN/SILVER OR EQUIV" at 11662,2392.64 h60
  text "OTHER" at 13093.46,2392.64 h60
  text "ARRAY/PANEL:" at 11332.46,2213.64 h60
  text "CUT AND TRIM PER MECH LAYER 1" at 12393.46,2209.35 h60
  text "N.C. ROUTE" at 12393.46,2057.64 h60
  text "X" at 13072.46,2057.64 h60
  text "V. SCORE" at 13259.46,2057.64 h60
  text "CERTIFICATION:" at 11332.46,1920.64 h60
  text "MATERIALS AND WORKMANSHIP FOR ALL PCBS" at 12057.46,1920.64 h60
  text "TO MEET OR EXCEED THE REQUIREMENTS OF:" at 12057.46,1822.64 h60
  text "X" at 11683.96,1686.13 h60
  text "ANSI IPC-A-600F CLASS ->" at 11822.96,1686.13 h60
  text "X" at 13462.02,1686.13 h60
  text "2" at 13580.96,1686.14 h60
  text "1" at 13265.96,1684.64 h60
  text "3" at 13934.96,1684.64 h60
  text "X" at 11686.02,1526.64 h60
  text "UL 94V-0" at 11822.96,1526.64 h60
  text "X" at 12498.02,1526.64 h60
  text "RoHS" at 12634.96,1526.64 h60
  text "OTHER" at 13279.36,1526.64 h60
  text "PER ORDER" at 13676.42,1526.64 h60
  text "ADDITIONAL REQUIREMENTS:" at 11332.46,1385.64 h60
  text "MICROSECTION:" at 11407.23,1270.64 h60
  text "YES" at 12312.96,1270.64 h60
  text "REQUIRED" at 13174.46,1114.49 h60
  text "BARE BOARD ELEC. TEST:" at 11407.23,1111.64 h60
  text "NONE" at 12712.96,1111.64 h60
  text "X" at 13047.46,1111.64 h60
  text "PER ORDER" at 13766.46,1111.64 h60
  text "MANUFACTURER'S UL:" at 11407.23,954.64 h60
  text "RAIL" at 12572.96,950.35 h60
  text "METAL" at 13064.77,950.35 h60
  text "X" at 13440,950 h60
  text "SILK" at 13576.46,950.35 h60
  text ".Layer_Name" at 577,-858.49 h60
M11 Gerber Information:
  lines w10: -292,-930.17 6308,-930.17 ; -292,-726.83 6310,-726.83 ; -292,-523.5 -292,-1133.5 3713,-1133.5 6310,-1133.5 6310,-523.5 -291.5,-523.5 -291.5,-1133.5 1284,-1133.5 ; 2173,-1133.5 2173,-523.5 ; 3440,-726.83 3440,-523.5 ; 4280,-726.83 4280,-523.5 ; 4902,-1140 4902,-937.17
  text "ALL ARTWORK VIEWED FROM TOP SIDE" at -228.5,-655.67 h60
  text "BOARD #:" at 2248,-655.67 h60
  text ".PRJ_Number" at 2793.5,-655.67 h60
  text "REV:" at 3638,-655.67 h60
  text ".PCB_Rev" at 3929.5,-655.67 h60
  text "SVN REV:" at 4476,-655.67 h60
  text ".VersionControl_RevNumber" at 4982,-655.67 h60
  text "LAYER NAME =" at -228.5,-858.49 h60
  text "PLOT NAME =" at -228.5,-1064.34 h60
  text ".plot_File_Name" at 577,-1064.34 h60
  text "GENERATED    :" at 2250,-1064.34 h60
  text ".Print_Date" at 3119.5,-1064.34 h60
  text ".Print_Time" at 3848.5,-1064.34 h60
  text "TEXAS INSTRUMENTS" at 5113,-1064.34 h60
M12 Stackup:
  lines w6: 11045,7704.25 14225,7704.25 ; 11045,7812.75 14225,7812.75 ; 10985,6975 ccw(c11020,6975) 11020,6940 14250,6940 ccw(c14250,6975) 14285,6975 14285,7920 ccw(c14250,7920) 14250,7955 11020,7955 ccw(c11020,7920) 10985,7920 10985,6975
  text "Layer Stack Up Detail for: ISE4016_E1.PcbDoc" at 11045,7843.67 h54
  text "Layer" at 11045,7772.25 h25
  text "Gerber" at 11726.81,7772.25 h25
  text "Copper" at 12069.59,7772.25 h25
  text "Dielectric" at 12453.19,7772.25 h25
  text "Dielectric" at 12854.29,7772.25 h25
  text "Dielectric" at 13361.16,7772.25 h25
  text "Dielectric" at 13762.26,7772.25 h25
  text "Name" at 11045,7722.25 h25
  text "Document" at 11726.81,7722.25 h25
  text "Thickness" at 12069.59,7722.25 h25
  text "Height" at 12453.19,7722.25 h25
  text "Material" at 12854.29,7722.25 h25
  text "Constant" at 13361.16,7722.25 h25
  text "Type" at 13762.26,7722.25 h25
  text "Top Solder Mask" at 11045,7648.39 h35
  text "(.GTS)" at 11726.81,7648.39 h35
  text "0.4mil" at 12453.19,7648.39 h35
  text "Solder Resist" at 12854.29,7648.39 h35
  text "3.50" at 13361.16,7648.39 h35
  text "Top Layer" at 11045,7542.66 h35
  text "(.GTL)" at 11726.81,7542.66 h35
  text "1.4mil" at 12069.59,7542.66 h35
  text "5.2mil" at 12453.19,7489.79 h35
  text "370 HR" at 12854.29,7489.79 h35
  text "4.80" at 13361.16,7489.79 h35
  text "PrePreg" at 13762.26,7489.79 h35
  text "InternalPlane1" at 11045,7436.93 h35
  text "(.GP1)" at 11726.81,7436.93 h35
  text "1.4mil" at 12069.59,7436.93 h35
  text "43mil" at 12453.19,7384.06 h35
  text "370 HR" at 12854.29,7384.06 h35
  text "4.80" at 13361.16,7384.06 h35
  text "Core" at 13762.26,7384.06 h35
  text "MidLayer2" at 11045,7331.2 h35
  text "(.G1)" at 11726.81,7331.2 h35
  text "1.4mil" at 12069.59,7331.2 h35
  text "5.2mil" at 12453.19,7278.33 h35
  text "370 HR" at 12854.29,7278.33 h35
  text "4.80" at 13361.16,7278.33 h35
  text "PrePreg" at 13762.26,7278.33 h35
  text "Bottom Layer" at 11045,7225.47 h35
  text "(.GBL)" at 11726.81,7225.47 h35
  text "1.4mil" at 12069.59,7225.47 h35
  text "Bottom Solder Mask" at 11045,7119.74 h35
  text "(.GBS)" at 11726.81,7119.74 h35
  text "0.4mil" at 12453.19,7119.74 h35
  text "Solder Resist" at 12854.29,7119.74 h35
  text "3.50" at 13361.16,7119.74 h35
  text ".Layer_Name" at 577,-858.49 h60
M13 Component Bodies Top:
  text ".Layer_Name" at 577,-858.49 h60
M14 Component Bodies Bottom:
  text ".Layer_Name" at 577,-858.49 h60
M15 Courtyards Top:
  text ".Layer_Name" at 577,-858.49 h60
M16 Courtyards Bottom:
  text ".Layer_Name" at 577,-858.49 h60
Drill Drawing:
  text ".legend" at 6130,810 h60
  text ".Layer_Name" at 577,-858.49 h60

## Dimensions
0,0 to 0,2000 on M2 Board Dimensions
0,0 to 5600,0 on M2 Board Dimensions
